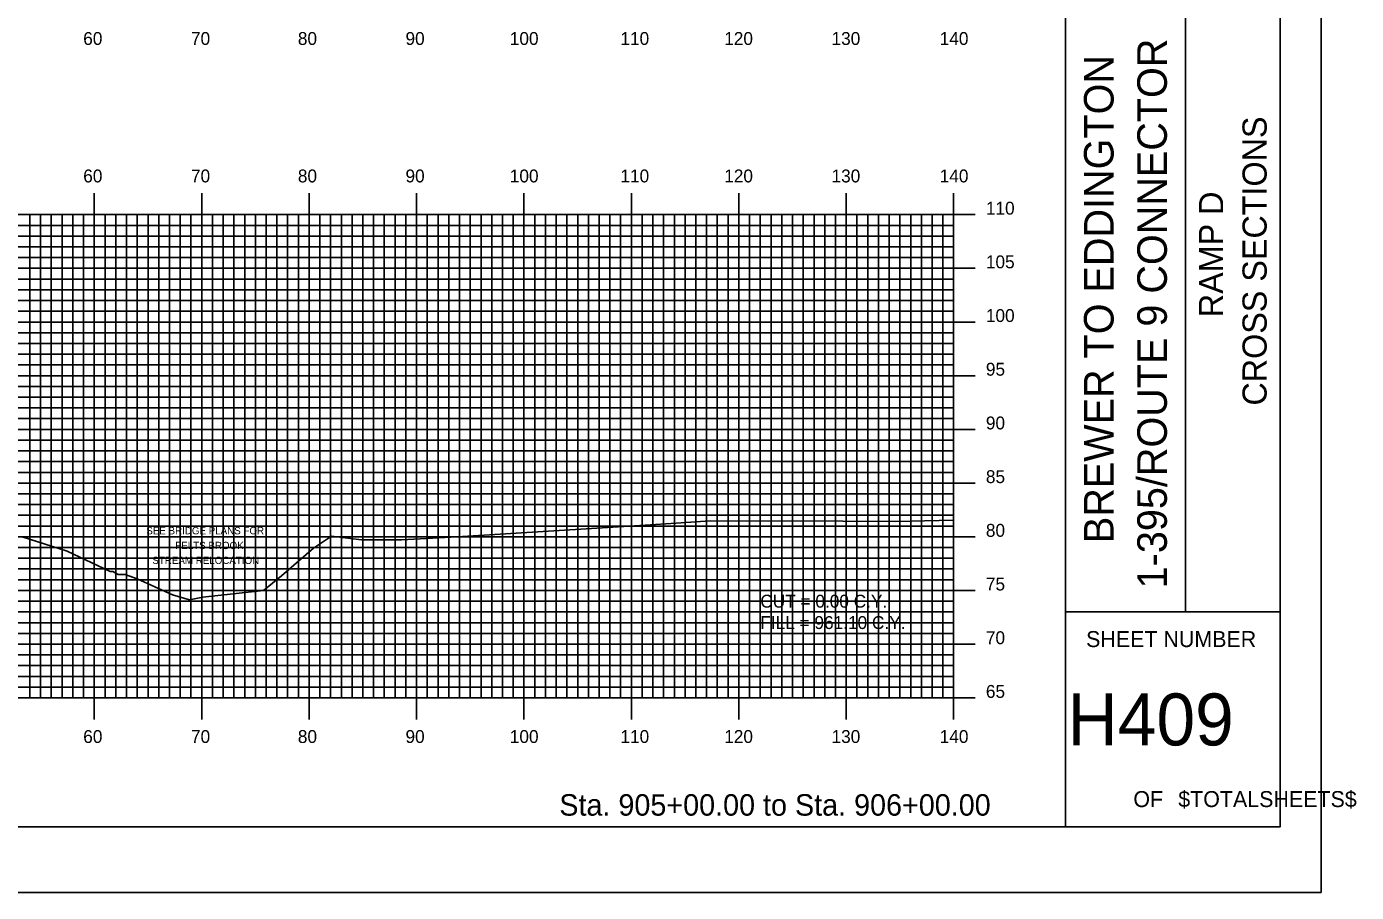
# Model space of a CAD drawing. Extents: x 857504 to 857847, y 364765 to 364985.
# Drawn here: x 857723 to 857846.8, y 364765.2 to 364845.8 of the extents above; entities that cross this region are included whole.
import ezdxf

# ---------------------------------------------------------------- set-up
doc = ezdxf.new("R2010")
doc.units = 0
for name, color, linetype in [('ANNOTATION', 7, 'Continuous'), ('BORDER', 7, 'Continuous'), ('D_Text_Standard', 7, 'Continuous'), ('H_V ANNOTATION', 7, 'Continuous'), ('MAJOR', 7, 'Continuous'), ('MINOR', 7, 'Continuous'), ('PLOT BOUNDARY', 7, 'Continuous'), ('S_Roadway_Centerline', 7, 'Continuous')]:
    doc.layers.add(name, color=color, linetype=linetype)

msp = doc.modelspace()

# ---------------------------------------------------------------- linework, layer by layer
at = {"layer": 'BORDER'}
for p, q in [((857819.71, 364771.3), (857819.71, 364981.3)), ((857830.89, 364791.31), (857830.89, 364861.31)), ((857819.71, 364791.31), (857839.71, 364791.31))]:
    msp.add_line(p, q, dxfattribs=at)
msp.add_lwpolyline([(857519.71, 364771.3), (857839.71, 364771.3), (857839.71, 364981.3), (857519.71, 364981.3)], close=True, dxfattribs=at)
at = {"layer": 'MAJOR'}
for p, q in [((857729.31, 364830.31), (857729.31, 364828.3)), ((857739.31, 364830.31), (857739.31, 364828.3)), ((857749.31, 364830.31), (857749.31, 364828.3)), ((857759.31, 364830.31), (857759.31, 364828.3)), ((857769.31, 364830.31), (857769.31, 364828.3)), ((857779.31, 364830.31), (857779.31, 364828.3)), ((857789.31, 364830.31), (857789.31, 364828.3)), ((857799.31, 364830.31), (857799.31, 364828.3)), ((857809.31, 364830.31), (857809.31, 364828.3)), ((857529.31, 364828.3), (857809.31, 364828.3)), ((857529.31, 364828.3), (857809.31, 364828.3)), ((857729.31, 364783.3), (857729.31, 364828.3)), ((857739.31, 364783.3), (857739.31, 364828.3)), ((857749.31, 364783.3), (857749.31, 364828.3)), ((857759.31, 364783.3), (857759.31, 364828.3)), ((857769.31, 364783.3), (857769.31, 364828.3)), ((857779.31, 364783.3), (857779.31, 364828.3)), ((857789.31, 364783.3), (857789.31, 364828.3)), ((857799.31, 364783.3), (857799.31, 364828.3)), ((857811.31, 364828.3), (857807.3, 364828.3)), ((857809.31, 364783.3), (857809.31, 364828.3)), ((857809.31, 364783.3), (857809.31, 364828.3)), ((857529.31, 364823.3), (857809.31, 364823.3)), ((857811.31, 364823.3), (857807.3, 364823.3)), ((857529.31, 364818.3), (857809.31, 364818.3)), ((857811.31, 364818.3), (857807.3, 364818.3)), ((857529.31, 364813.3), (857809.31, 364813.3)), ((857811.31, 364813.3), (857807.3, 364813.3)), ((857529.31, 364808.3), (857809.31, 364808.3)), ((857811.31, 364808.3), (857807.3, 364808.3)), ((857529.31, 364803.3), (857809.31, 364803.3)), ((857811.31, 364803.3), (857807.3, 364803.3)), ((857529.31, 364798.3), (857809.31, 364798.3)), ((857811.31, 364798.3), (857807.3, 364798.3)), ((857529.31, 364793.3), (857809.31, 364793.3)), ((857811.31, 364793.3), (857807.3, 364793.3)), ((857529.31, 364788.3), (857809.31, 364788.3)), ((857811.31, 364788.3), (857807.3, 364788.3)), ((857529.31, 364783.3), (857809.31, 364783.3)), ((857529.31, 364783.3), (857809.31, 364783.3)), ((857729.31, 364781.3), (857729.31, 364783.3)), ((857739.31, 364781.3), (857739.31, 364783.3)), ((857749.31, 364781.3), (857749.31, 364783.3)), ((857759.31, 364781.3), (857759.31, 364783.3)), ((857769.31, 364781.3), (857769.31, 364783.3)), ((857779.31, 364781.3), (857779.31, 364783.3)), ((857789.31, 364781.3), (857789.31, 364783.3)), ((857799.31, 364781.3), (857799.31, 364783.3)), ((857811.31, 364783.3), (857807.3, 364783.3)), ((857809.31, 364781.3), (857809.31, 364783.3))]:
    msp.add_line(p, q, dxfattribs=at)
at = {"layer": 'MINOR'}
for p, q in [((857723.31, 364783.3), (857723.31, 364828.3)), ((857724.31, 364783.3), (857724.31, 364828.3)), ((857725.31, 364783.3), (857725.31, 364828.3)), ((857726.31, 364783.3), (857726.31, 364828.3)), ((857727.31, 364783.3), (857727.31, 364828.3)), ((857728.31, 364783.3), (857728.31, 364828.3)), ((857730.31, 364783.3), (857730.31, 364828.3)), ((857731.31, 364783.3), (857731.31, 364828.3)), ((857732.31, 364783.3), (857732.31, 364828.3)), ((857733.31, 364783.3), (857733.31, 364828.3)), ((857734.31, 364783.3), (857734.31, 364828.3)), ((857735.31, 364783.3), (857735.31, 364828.3)), ((857736.31, 364783.3), (857736.31, 364828.3)), ((857737.31, 364783.3), (857737.31, 364828.3)), ((857738.31, 364783.3), (857738.31, 364828.3)), ((857740.31, 364783.3), (857740.31, 364828.3)), ((857741.31, 364783.3), (857741.31, 364828.3)), ((857742.31, 364783.3), (857742.31, 364828.3)), ((857743.31, 364783.3), (857743.31, 364828.3)), ((857744.31, 364783.3), (857744.31, 364828.3)), ((857745.31, 364783.3), (857745.31, 364828.3)), ((857746.31, 364783.3), (857746.31, 364828.3)), ((857747.31, 364783.3), (857747.31, 364828.3)), ((857748.31, 364783.3), (857748.31, 364828.3)), ((857750.31, 364783.3), (857750.31, 364828.3)), ((857751.31, 364783.3), (857751.31, 364828.3)), ((857752.31, 364783.3), (857752.31, 364828.3)), ((857753.31, 364783.3), (857753.31, 364828.3)), ((857754.31, 364783.3), (857754.31, 364828.3)), ((857755.31, 364783.3), (857755.31, 364828.3)), ((857756.31, 364783.3), (857756.31, 364828.3)), ((857757.31, 364783.3), (857757.31, 364828.3)), ((857758.31, 364783.3), (857758.31, 364828.3)), ((857760.31, 364783.3), (857760.31, 364828.3)), ((857761.31, 364783.3), (857761.31, 364828.3)), ((857762.31, 364783.3), (857762.31, 364828.3)), ((857763.31, 364783.3), (857763.31, 364828.3)), ((857764.31, 364783.3), (857764.31, 364828.3)), ((857765.31, 364783.3), (857765.31, 364828.3)), ((857766.31, 364783.3), (857766.31, 364828.3)), ((857767.31, 364783.3), (857767.31, 364828.3)), ((857768.31, 364783.3), (857768.31, 364828.3)), ((857770.31, 364783.3), (857770.31, 364828.3)), ((857771.31, 364783.3), (857771.31, 364828.3)), ((857772.31, 364783.3), (857772.31, 364828.3)), ((857773.31, 364783.3), (857773.31, 364828.3)), ((857774.31, 364783.3), (857774.31, 364828.3)), ((857775.31, 364783.3), (857775.31, 364828.3)), ((857776.31, 364783.3), (857776.31, 364828.3)), ((857777.31, 364783.3), (857777.31, 364828.3)), ((857778.31, 364783.3), (857778.31, 364828.3)), ((857780.31, 364783.3), (857780.31, 364828.3)), ((857781.31, 364783.3), (857781.31, 364828.3)), ((857782.31, 364783.3), (857782.31, 364828.3)), ((857783.31, 364783.3), (857783.31, 364828.3)), ((857784.31, 364783.3), (857784.31, 364828.3)), ((857785.31, 364783.3), (857785.31, 364828.3)), ((857786.31, 364783.3), (857786.31, 364828.3)), ((857787.31, 364783.3), (857787.31, 364828.3)), ((857788.31, 364783.3), (857788.31, 364828.3)), ((857790.31, 364783.3), (857790.31, 364828.3)), ((857791.31, 364783.3), (857791.31, 364828.3)), ((857792.31, 364783.3), (857792.31, 364828.3)), ((857793.31, 364783.3), (857793.31, 364828.3)), ((857794.31, 364783.3), (857794.31, 364828.3)), ((857795.31, 364783.3), (857795.31, 364828.3)), ((857796.31, 364783.3), (857796.31, 364828.3)), ((857797.31, 364783.3), (857797.31, 364828.3)), ((857798.31, 364783.3), (857798.31, 364828.3)), ((857800.31, 364783.3), (857800.31, 364828.3)), ((857801.31, 364783.3), (857801.31, 364828.3)), ((857802.31, 364783.3), (857802.31, 364828.3)), ((857803.31, 364783.3), (857803.31, 364828.3)), ((857804.31, 364783.3), (857804.31, 364828.3)), ((857805.31, 364783.3), (857805.31, 364828.3)), ((857806.31, 364783.3), (857806.31, 364828.3)), ((857807.31, 364783.3), (857807.31, 364828.3)), ((857808.31, 364783.3), (857808.31, 364828.3)), ((857529.31, 364827.3), (857809.31, 364827.3)), ((857809.31, 364827.3), (857807.3, 364827.3)), ((857529.31, 364826.3), (857809.31, 364826.3)), ((857809.31, 364826.3), (857807.3, 364826.3)), ((857529.31, 364825.3), (857809.31, 364825.3)), ((857529.31, 364824.3), (857809.31, 364824.3)), ((857809.31, 364825.3), (857807.3, 364825.3)), ((857809.31, 364824.3), (857807.3, 364824.3)), ((857529.31, 364822.3), (857809.31, 364822.3)), ((857809.31, 364822.3), (857807.3, 364822.3)), ((857529.31, 364821.3), (857809.31, 364821.3)), ((857809.31, 364821.3), (857807.3, 364821.3)), ((857529.31, 364820.3), (857809.31, 364820.3)), ((857529.31, 364819.3), (857809.31, 364819.3)), ((857809.31, 364820.3), (857807.3, 364820.3)), ((857809.31, 364819.3), (857807.3, 364819.3)), ((857529.31, 364817.3), (857809.31, 364817.3)), ((857809.31, 364817.3), (857807.3, 364817.3)), ((857529.31, 364816.3), (857809.31, 364816.3)), ((857809.31, 364816.3), (857807.3, 364816.3)), ((857529.31, 364815.3), (857809.31, 364815.3)), ((857529.31, 364814.3), (857809.31, 364814.3)), ((857809.31, 364815.3), (857807.3, 364815.3)), ((857809.31, 364814.3), (857807.3, 364814.3)), ((857529.31, 364812.3), (857809.31, 364812.3)), ((857809.31, 364812.3), (857807.3, 364812.3)), ((857529.31, 364811.3), (857809.31, 364811.3)), ((857809.31, 364811.3), (857807.3, 364811.3)), ((857529.31, 364810.3), (857809.31, 364810.3)), ((857529.31, 364809.3), (857809.31, 364809.3)), ((857809.31, 364810.3), (857807.3, 364810.3)), ((857809.31, 364809.3), (857807.3, 364809.3)), ((857529.31, 364807.3), (857809.31, 364807.3)), ((857809.31, 364807.3), (857807.3, 364807.3)), ((857529.31, 364806.3), (857809.31, 364806.3)), ((857809.31, 364806.3), (857807.3, 364806.3)), ((857529.31, 364805.3), (857809.31, 364805.3)), ((857529.31, 364804.3), (857809.31, 364804.3)), ((857809.31, 364805.3), (857807.3, 364805.3)), ((857809.31, 364804.3), (857807.3, 364804.3)), ((857529.31, 364802.3), (857809.31, 364802.3)), ((857809.31, 364802.3), (857807.3, 364802.3)), ((857529.31, 364801.3), (857809.31, 364801.3)), ((857809.31, 364801.3), (857807.3, 364801.3)), ((857529.31, 364800.3), (857809.31, 364800.3)), ((857809.31, 364800.3), (857807.3, 364800.3)), ((857529.31, 364799.3), (857809.31, 364799.3)), ((857809.31, 364799.3), (857807.3, 364799.3)), ((857529.31, 364797.3), (857809.31, 364797.3)), ((857809.31, 364797.3), (857807.3, 364797.3)), ((857529.31, 364796.3), (857809.31, 364796.3)), ((857809.31, 364796.3), (857807.3, 364796.3)), ((857529.31, 364795.3), (857809.31, 364795.3)), ((857809.31, 364795.3), (857807.3, 364795.3)), ((857529.31, 364794.3), (857809.31, 364794.3)), ((857809.31, 364794.3), (857807.3, 364794.3)), ((857529.31, 364792.3), (857809.31, 364792.3)), ((857809.31, 364792.3), (857807.3, 364792.3)), ((857529.31, 364791.3), (857809.31, 364791.3)), ((857809.31, 364791.3), (857807.3, 364791.3)), ((857529.31, 364790.3), (857809.31, 364790.3)), ((857809.31, 364790.3), (857807.3, 364790.3)), ((857529.31, 364789.3), (857809.31, 364789.3)), ((857809.31, 364789.3), (857807.3, 364789.3)), ((857529.31, 364787.3), (857809.31, 364787.3)), ((857809.31, 364787.3), (857807.3, 364787.3)), ((857529.31, 364786.3), (857809.31, 364786.3)), ((857809.31, 364786.3), (857807.3, 364786.3)), ((857529.31, 364785.3), (857809.31, 364785.3)), ((857809.31, 364785.3), (857807.3, 364785.3)), ((857529.31, 364784.3), (857809.31, 364784.3)), ((857809.31, 364784.3), (857807.3, 364784.3))]:
    msp.add_line(p, q, dxfattribs=at)
at = {"layer": 'PLOT BOUNDARY'}
msp.add_lwpolyline([(857503.52, 364765.18), (857843.52, 364765.18), (857843.52, 364985.18), (857503.52, 364985.18)], close=True, dxfattribs=at)
at = {"layer": 'S_Roadway_Centerline'}
msp.add_lwpolyline([(857722.59, 364798.3), (857726.78, 364796.97), (857730.8, 364795.07), (857731.03, 364795.07), (857731.54, 364794.8), (857732.19, 364794.78), (857733.31, 364794.37), (857736.6, 364792.9), (857738.18, 364792.43), (857739.42, 364792.68), (857745.05, 364793.3), (857746.73, 364794.66), (857749.72, 364797.23), (857751.4, 364798.35), (857754.19, 364798.03), (857757.92, 364798.01), (857763.08, 364798.28), (857780.58, 364799.39), (857783.47, 364799.56), (857786.63, 364799.78), (857798.99, 364799.76), (857803.89, 364799.73), (857807.97, 364799.82), (857809.31, 364799.84)], dxfattribs=at)

# ---------------------------------------------------------------- texts
at = {"layer": 'ANNOTATION'}
for s, p in [('SEE BRIDGE PLANS FOR', (857734.15, 364798.53)), ('FELTS BROOK ', (857736.85, 364797.15)), ('STREAM RELOCATION', (857734.71, 364795.77))]:
    msp.add_text(s, height=0.68, dxfattribs=at).set_placement(p)
at = {"layer": 'BORDER'}
for s, height, p in [('1-395/ROUTE 9 CONNECTOR', 2.7557, (857829.16, 364793.5)), ('BREWER TO EDDINGTON', 2.7557, (857824.2, 364797.71)), ('CROSS SECTIONS', 2.25, (857838.45, 364810.52)), ('RAMP D', 2.25, (857834.4, 364818.75))]:
    msp.add_text(s, height=height, rotation=90, dxfattribs=at).set_placement(p)
for s, height, p in [('SHEET NUMBER', 1.4905, (857821.64, 364788.03)), ('H409', 4.839, (857819.92, 364778.87)), ('OF', 1.491, (857826.04, 364773.13)), ('$TOTALSHEETS$', 1.4905, (857830.22, 364773.13))]:
    msp.add_text(s, height=height, dxfattribs=at).set_placement(p)
at = {"layer": 'D_Text_Standard'}
for s, p in [('CUT = 0.00 C.Y.', (857791.31, 364791.7)), ('FILL = 961.10 C.Y.', (857791.31, 364789.71))]:
    msp.add_text(s, height=1.2, dxfattribs=at).set_placement(p)
at = {"layer": 'H_V ANNOTATION'}
for s, height, p in [('60', 1.2, (857728.28, 364844.1)), ('70', 1.2, (857738.31, 364844.1)), ('80', 1.2, (857748.26, 364844.1)), ('90', 1.2, (857758.28, 364844.1)), ('100', 1.2, (857767.99, 364844.1)), ('110', 1.2, (857778.29, 364844.1)), ('120', 1.2, (857787.95, 364844.1)), ('130', 1.2, (857797.94, 364844.1)), ('140', 1.2, (857808.01, 364844.1)), ('60', 1.2, (857728.28, 364831.3)), ('70', 1.2, (857738.31, 364831.3)), ('80', 1.2, (857748.26, 364831.3)), ('90', 1.2, (857758.28, 364831.3)), ('100', 1.2, (857767.99, 364831.3)), ('110', 1.2, (857778.29, 364831.3)), ('120', 1.2, (857787.95, 364831.3)), ('130', 1.2, (857797.94, 364831.3)), ('140', 1.2, (857808.01, 364831.3)), ('110', 1.2, (857812.31, 364828.3)), ('105', 1.2, (857812.31, 364823.3)), ('100', 1.2, (857812.31, 364818.3)), ('95', 1.2, (857812.31, 364813.3)), ('90', 1.2, (857812.31, 364808.3)), ('85', 1.2, (857812.31, 364803.3)), ('80', 1.2, (857812.31, 364798.3)), ('75', 1.2, (857812.31, 364793.3)), ('70', 1.2, (857812.31, 364788.3)), ('65', 1.2, (857812.31, 364783.3)), ('60', 1.2, (857728.28, 364779.1)), ('70', 1.2, (857738.31, 364779.1)), ('80', 1.2, (857748.26, 364779.1)), ('90', 1.2, (857758.28, 364779.1)), ('100', 1.2, (857767.99, 364779.1)), ('110', 1.2, (857778.29, 364779.1)), ('120', 1.2, (857787.95, 364779.1)), ('130', 1.2, (857797.94, 364779.1)), ('140', 1.2, (857808.01, 364779.1)), ('Sta. 905+00.00 to Sta. 906+00.00', 2.0004, (857772.6, 364772.33))]:
    msp.add_text(s, height=height, dxfattribs=at).set_placement(p)

doc.saveas('drawing.dxf')
